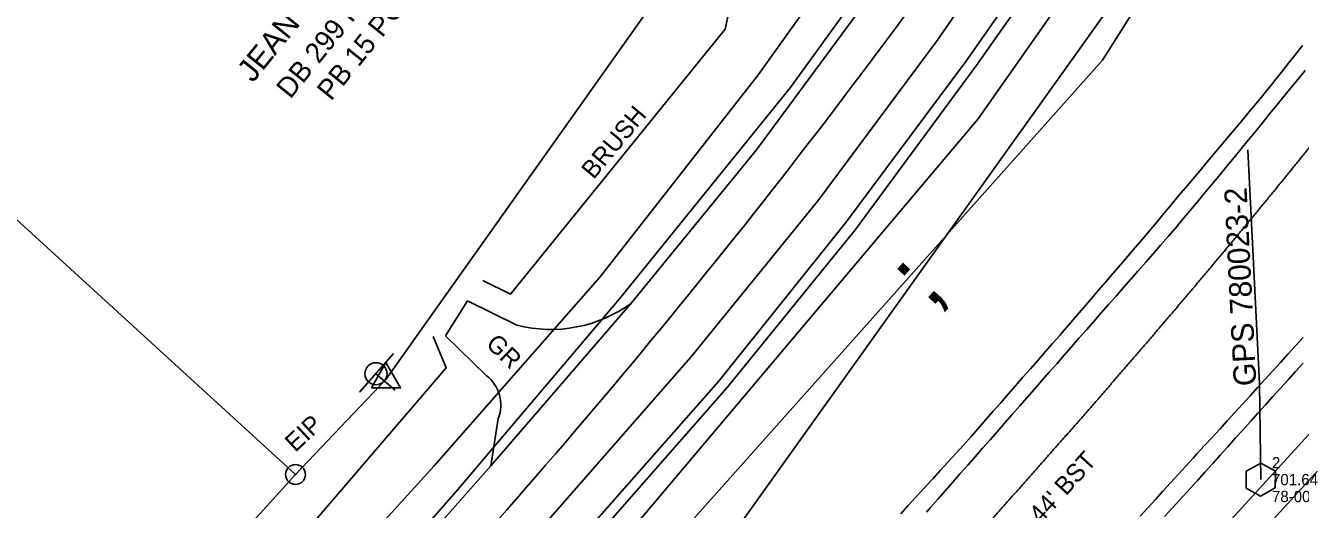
# Model space of a CAD drawing. Extents: x 1806071 to 1809844, y 912722 to 917035.
# Drawn here: x 1807079 to 1807362.2, y 914124 to 914231.7 of the extents above; entities that cross this region are included whole.
import ezdxf

# ---------------------------------------------------------------- set-up
doc = ezdxf.new("R2010")
doc.units = 0
for name, color, linetype in [('CTL GPS Vertical CELL', 7, 'Continuous'), ('CTL GPS Vertical Cogo Comment', 7, 'Continuous'), ('CTL GPS Vertical Cogo Elevation', 7, 'Continuous'), ('CTL GPS Vertical Cogo Number', 7, 'Continuous'), ('Exist Guardrail', 7, 'Continuous'), ('Exist Horizontal Alignment', 7, 'Continuous'), ('Exist Horizontal Alignment Station Label', 7, 'Continuous'), ('Exist Other Culture Fence Line', 7, 'Continuous'), ('Exist Property Deed Book Text', 7, 'Continuous'), ('Exist Property Iron Pin CELL', 7, 'Continuous'), ('Exist Property Iron Pin Text', 7, 'Continuous'), ('Exist Property Line', 7, 'Continuous'), ('Exist Property Owner Text', 7, 'Continuous'), ('Exist Right of Way Control of Access CA Symbol CELL', 7, 'Continuous'), ('Exist Right of Way Line', 7, 'Continuous'), ('Exist Right of Way Monument CELL', 7, 'Continuous'), ('Exist Roads EOP', 7, 'Continuous'), ('Exist Roads EOP Text', 7, 'Continuous'), ('Exist Roads EOT', 7, 'Continuous'), ('Exist Roads Soil', 7, 'Continuous'), ('Exist Roads Soil Text', 7, 'Continuous'), ('Exist Structure Minor Pipes RCP 24 Inch', 7, 'Continuous'), ('Exist Utilities Power Joint Use Telephone CELL', 7, 'Continuous'), ('Exist Utilities Telephone UG Cable SUE LOS B', 7, 'Continuous'), ('Exist Utilities Water UG Line SUE LOS B', 7, 'Continuous'), ('Exist Vegetation Hedge Row', 7, 'Continuous'), ('Exist Vegetation Hedge Row Text', 7, 'Continuous'), ('Exist Vegetation Woods Line', 7, 'Continuous')]:
    doc.layers.add(name, color=color, linetype=linetype)

msp = doc.modelspace()

# ---------------------------------------------------------------- linework, layer by layer
at = {"layer": 'CTL GPS Vertical CELL'}
msp.add_line((1807353.38, 914130.67), (1807353.38, 914130.67), dxfattribs=at)
msp.add_lwpolyline([(1807350.15, 914132.55), (1807353.4, 914134.36), (1807356.65, 914132.57), (1807356.6, 914128.85), (1807353.35, 914126.96), (1807350.15, 914128.77)], close=True, dxfattribs=at)
at = {"layer": 'Exist Guardrail'}
msp.add_lwpolyline([(1807384.69, 914379.78), (1807359.93, 914333.62), (1807343.17, 914305.53), (1807317.15, 914265.55), (1807287.85, 914223.71), (1807261.22, 914187.88), (1807232.95, 914152.51), (1807202.11, 914117.44), (1807168.59, 914080.84), (1807134.41, 914043.78), (1807102.1, 914008.78), (1807070.61, 913974.53), (1807044.54, 913946.19), (1807011.35, 913910), (1806981.15, 913877.01), (1806950.16, 913843.21)], dxfattribs=at)
at = {"layer": 'Exist Horizontal Alignment'}
msp.add_line((1806073.69, 912724.84), (1809374.2, 916346.52), dxfattribs=at)
for centre, radius, start, end in [((1805945.49, 915212), 1650, 317.71257, 325.04077), ((1806875.73, 914308.35), 954.93, 296.15643, 355.38963)]:
    msp.add_arc(centre, radius, start, end, dxfattribs=at)
msp.add_spline([(1807240.45, 914063.04), (1807242.27, 914065.04), (1807244.1, 914067.04), (1807245.92, 914069.04), (1807247.74, 914071.03), (1807249.56, 914073.03), (1807251.38, 914075.03), (1807253.19, 914077.03), (1807255.01, 914079.03), (1807256.83, 914081.03), (1807258.65, 914083.03), (1807260.47, 914085.03), (1807262.29, 914087.03), (1807264.1, 914089.03), (1807265.92, 914091.03), (1807267.73, 914093.03), (1807269.55, 914095.04), (1807271.36, 914097.04), (1807273.17, 914099.05), (1807274.99, 914101.05), (1807276.8, 914103.06), (1807278.61, 914105.06), (1807280.41, 914107.07), (1807282.22, 914109.08), (1807284.03, 914111.09), (1807285.83, 914113.1), (1807287.64, 914115.12), (1807289.44, 914117.13), (1807291.24, 914119.15), (1807293.04, 914121.16), (1807294.84, 914123.18), (1807296.64, 914125.2), (1807298.43, 914127.22), (1807300.22, 914129.24), (1807302.02, 914131.26), (1807303.81, 914133.29), (1807305.59, 914135.32), (1807307.38, 914137.34), (1807309.16, 914139.37), (1807310.95, 914141.41), (1807312.73, 914143.44), (1807314.51, 914145.47), (1807316.28, 914147.51), (1807318.06, 914149.55), (1807319.83, 914151.59), (1807321.6, 914153.63), (1807323.36, 914155.68), (1807325.13, 914157.73), (1807326.89, 914159.78), (1807328.65, 914161.83), (1807330.41, 914163.88), (1807332.16, 914165.94), (1807333.91, 914167.99), (1807335.66, 914170.05), (1807337.41, 914172.12), (1807339.15, 914174.18), (1807340.89, 914176.25), (1807342.63, 914178.32), (1807344.37, 914180.39), (1807346.1, 914182.47), (1807347.83, 914184.55), (1807349.55, 914186.63), (1807351.27, 914188.71), (1807352.99, 914190.79), (1807354.71, 914192.88), (1807356.42, 914194.97), (1807358.13, 914197.07), (1807359.83, 914199.17), (1807361.54, 914201.27), (1807363.23, 914203.37), (1807364.93, 914205.47), (1807366.62, 914207.58), (1807368.3, 914209.7), (1807369.99, 914211.81), (1807371.67, 914213.93)], degree=3, dxfattribs=at)
at = {"layer": 'Exist Horizontal Alignment Station Label'}
for p, q in [((1807353.1, 914152.01), (1807350.52, 914204)), ((1807353.38, 914130.67), (1807353.1, 914152.01))]:
    msp.add_line(p, q, dxfattribs=at)
at = {"layer": 'Exist Other Culture Fence Line'}
msp.add_lwpolyline([(1806951.65, 913841.13), (1806983.44, 913875.99), (1807013.14, 913908.4), (1807047.06, 913945.66), (1807072.1, 913972.65), (1807103.97, 914007.22), (1807136.36, 914042.6), (1807170.27, 914079.29), (1807203.63, 914115.49), (1807234.9, 914151.15), (1807263.39, 914186.29), (1807290.32, 914222.94), (1807319.14, 914263.94), (1807345.33, 914304.29), (1807362.24, 914332.3), (1807387.67, 914379.81), (1807420.06, 914449.08)], dxfattribs=at)
at = {"layer": 'Exist Property Iron Pin CELL'}
for radius in [2.2, 0.0707]:
    msp.add_circle((1807138.99, 914131.81), radius, dxfattribs=at)
at = {"layer": 'Exist Property Line'}
msp.add_line((1807138.99, 914131.81), (1806985.27, 914272.46), dxfattribs=at)
at = {"layer": 'Exist Right of Way Control of Access CA Symbol CELL'}
msp.add_line((1807279.4, 914178.99), (1807279.4, 914178.99), dxfattribs=at)
at = {"layer": 'Exist Right of Way Line'}
for p, q in [((1807213.85, 914087.29), (1807408.46, 914360.2)), ((1807138.99, 914131.81), (1807072.09, 914058.26))]:
    msp.add_line(p, q, dxfattribs=at)
msp.add_lwpolyline([(1807235.62, 914261.04), (1807159.09, 914152.97), (1807138.99, 914131.81)], dxfattribs=at)
at = {"layer": 'Exist Right of Way Monument CELL'}
msp.add_line((1807159.09, 914152.97), (1807159.09, 914152.97), dxfattribs=at)
msp.add_lwpolyline([(1807155.84, 914151.08), (1807159.09, 914156.72), (1807162.34, 914151.08)], close=True, dxfattribs=at)
at = {"layer": 'Exist Roads EOP'}
msp.add_line((1807182.36, 914133.76), (1807213.6, 914169.96), dxfattribs=at)
for points in [[(1807255.1, 914192.79), (1807281.5, 914228.36), (1807309.99, 914269.65)], [(1807213.6, 914169.96), (1807241.42, 914204.04), (1807266.24, 914237.81), (1807268.12, 914240.61)], [(1807362.69, 914227.2), (1807361.13, 914225.24), (1807359.58, 914223.28), (1807358.02, 914221.33), (1807356.47, 914219.37), (1807356.32, 914219.18), (1807354.74, 914217.25), (1807353.16, 914215.32), (1807351.57, 914213.38), (1807351.14, 914212.85), (1807349.53, 914210.94), (1807347.93, 914209.02), (1807346.32, 914207.1), (1807344.72, 914205.19), (1807343.11, 914203.27), (1807341.51, 914201.36), (1807339.9, 914199.44), (1807338.3, 914197.52), (1807336.69, 914195.61), (1807335.08, 914193.69), (1807333.48, 914191.77), (1807331.87, 914189.86), (1807330.27, 914187.94), (1807328.66, 914186.02), (1807327.11, 914184.17), (1807325.48, 914182.27), (1807323.85, 914180.37), (1807322.23, 914178.47), (1807320.6, 914176.58), (1807318.97, 914174.68), (1807317.34, 914172.78), (1807315.72, 914170.88), (1807314.09, 914168.99), (1807312.46, 914167.09), (1807310.83, 914165.19), (1807309.21, 914163.29), (1807308.81, 914162.83), (1807307.16, 914160.95), (1807305.51, 914159.07), (1807303.87, 914157.19), (1807302.22, 914155.31), (1807300.57, 914153.43), (1807298.93, 914151.55), (1807297.28, 914149.67), (1807295.63, 914147.79), (1807293.98, 914145.9), (1807292.34, 914144.02), (1807290.69, 914142.14), (1807289.04, 914140.26), (1807287.34, 914138.32), (1807285.65, 914136.47), (1807283.97, 914134.62), (1807282.28, 914132.78), (1807280.6, 914130.93), (1807280.16, 914130.45), (1807278.48, 914128.6), (1807276.8, 914126.75), (1807275.11, 914124.9), (1807273.43, 914123.05)], [(1806945.72, 913846.49), (1806977.27, 913880.57), (1807007.52, 913913.78), (1807040.2, 913949.97), (1807065.65, 913978.22), (1807097.4, 914012.45), (1807129.79, 914047.7), (1807164, 914085.55), (1807196.13, 914122.85), (1807226.78, 914157.88), (1807255.1, 914192.79)], [(1807332, 914122.47), (1807333.69, 914124.31), (1807335.38, 914126.15), (1807337.07, 914127.99), (1807337.72, 914128.7), (1807339.39, 914130.56), (1807341.06, 914132.42), (1807342.73, 914134.28), (1807344.4, 914136.14), (1807346.07, 914138), (1807347.74, 914139.86), (1807349.41, 914141.71), (1807351.09, 914143.57), (1807352.76, 914145.43), (1807354.43, 914147.29), (1807356.1, 914149.15), (1807357.77, 914151.01), (1807359.44, 914152.87), (1807361.11, 914154.73), (1807362.79, 914156.59)], [(1807052.3, 913989.42), (1807084.47, 914024.84), (1807116.4, 914060.3), (1807150.94, 914098.08), (1807182.36, 914133.76)]]:
    msp.add_lwpolyline(points, dxfattribs=at)
at = {"layer": 'Exist Roads EOT'}
for points in [[(1807279.13, 914123.44), (1807280.07, 914124.49), (1807281.72, 914126.37), (1807283.36, 914128.25), (1807285.01, 914130.13), (1807286.66, 914132.01), (1807288.31, 914133.89), (1807289.95, 914135.77), (1807291.6, 914137.65), (1807293.25, 914139.53), (1807294.89, 914141.41), (1807296.54, 914143.29), (1807298.19, 914145.17), (1807299.84, 914147.05), (1807301.48, 914148.93), (1807303.13, 914150.81), (1807304.78, 914152.7), (1807306.42, 914154.58), (1807308.07, 914156.46), (1807309.72, 914158.34), (1807311.37, 914160.22), (1807313.01, 914162.1), (1807314.66, 914163.98), (1807316.31, 914165.86), (1807317.96, 914167.74), (1807319.6, 914169.62), (1807321.25, 914171.5), (1807322.9, 914173.38), (1807324.54, 914175.26), (1807326.19, 914177.14), (1807327.84, 914179.02), (1807329.49, 914180.9), (1807331.13, 914182.79), (1807332.83, 914184.72), (1807334.43, 914186.64), (1807336.03, 914188.56), (1807337.63, 914190.48), (1807339.23, 914192.4), (1807340.84, 914194.32), (1807342.44, 914196.24), (1807344.04, 914198.16), (1807345.64, 914200.07), (1807345.89, 914200.37), (1807347.46, 914202.31), (1807349.04, 914204.24), (1807350.62, 914206.18), (1807352.2, 914208.12), (1807353.78, 914210.06), (1807355.36, 914212), (1807356.94, 914213.94), (1807358.52, 914215.87), (1807360.09, 914217.81), (1807361.67, 914219.75), (1807363.25, 914221.69)], [(1807326.62, 914122.54), (1807328.3, 914124.39), (1807329.98, 914126.24), (1807331.67, 914128.09), (1807333.35, 914129.93), (1807335.03, 914131.78), (1807336.71, 914133.63), (1807338.4, 914135.48), (1807339.22, 914136.39), (1807340.91, 914138.24), (1807342.59, 914140.08), (1807344.28, 914141.93), (1807345.96, 914143.78), (1807347.65, 914145.63), (1807349.33, 914147.47), (1807351.01, 914149.32), (1807352.7, 914151.17), (1807354.38, 914153.02), (1807356.07, 914154.86), (1807357.75, 914156.71), (1807359.43, 914158.56), (1807361.12, 914160.41), (1807362.8, 914162.25)]]:
    msp.add_lwpolyline(points, dxfattribs=at)
at = {"layer": 'Exist Roads Soil'}
for p, q in [((1807172.32, 914162.65), (1807177.23, 914170.46)), ((1807188.16, 914165.04), (1807177.23, 914170.46)), ((1807181.37, 914153.83), (1807172.32, 914162.65)), ((1807182.36, 914133.76), (1807184.03, 914144.24))]:
    msp.add_line(p, q, dxfattribs=at)
for centre, major_axis, ratio, start_param, end_param in [((1807195.71, 914194.22), (29.39, -6.7), 0.999951, 4.683135, 5.571692), ((1807176.31, 914147.26), (6.52, 5.13), 0.998641, 5.242809, 6.530809)]:
    msp.add_ellipse(centre, major_axis=major_axis, ratio=ratio, start_param=start_param, end_param=end_param, dxfattribs=at)
at = {"layer": 'Exist Structure Minor Pipes RCP 24 Inch'}
msp.add_line((1807298.31, 914058.62), (1807569.06, 914354.69), dxfattribs=at)
at = {"layer": 'Exist Utilities Power Joint Use Telephone CELL'}
msp.add_line((1807156.87, 914154.23), (1807156.87, 914154.23), dxfattribs=at)
msp.add_lwpolyline([(1807160.76, 914158.71), (1807153.3, 914150.18), (1807156.85, 914154.24), (1807161.12, 914150.54)], dxfattribs=at)
msp.add_circle((1807156.87, 914154.22), 2.45, dxfattribs=at)
at = {"layer": 'Exist Utilities Telephone UG Cable SUE LOS B'}
msp.add_lwpolyline([(1807023.9, 913961.8), (1807061.37, 914001.94), (1807102.69, 914047), (1807137.71, 914085.93), (1807174.65, 914128.03), (1807210.98, 914170.85), (1807248.89, 914217.78), (1807283.52, 914265.76), (1807309.87, 914305.3), (1807337.23, 914356.7), (1807347.09, 914377.33), (1807353.51, 914402.93), (1807353.58, 914404.22)], dxfattribs=at)
at = {"layer": 'Exist Utilities Water UG Line SUE LOS B'}
msp.add_lwpolyline([(1806934.01, 913876.79), (1806942.74, 913886.69), (1806979.16, 913924.81), (1807020.1, 913968.31), (1807057.54, 914008.89), (1807096.91, 914053.52), (1807130.38, 914090.29), (1807169.81, 914133.74), (1807206.7, 914175.78), (1807241.81, 914220.76), (1807276.28, 914269.15), (1807304.66, 914309.76), (1807334.37, 914357.07), (1807347.65, 914376.89), (1807360.82, 914396.29), (1807368.31, 914413.26), (1807386.71, 914435.17), (1807414.54, 914474.63), (1807431.02, 914499.69)], dxfattribs=at)
at = {"layer": 'Exist Vegetation Hedge Row'}
for points in [[(1807235.73, 914237.2), (1807234.42, 914230.83), (1807186.75, 914171.96), (1807180.61, 914174.94)], [(1807169.58, 914162.49), (1807172.43, 914155.55), (1807089.9, 914059.13), (1807082.69, 914064.35)]]:
    msp.add_lwpolyline(points, dxfattribs=at)
at = {"layer": 'Exist Vegetation Woods Line'}
for points in [[(1806971.08, 913843.97), (1807045.94, 913927.81), (1807101.46, 913994.42), (1807207.65, 914112.42), (1807290.59, 914210.89), (1807368.19, 914321.69), (1807398.66, 914385.06), (1807410.19, 914406.72), (1807422.39, 914418.16), (1807425.9, 914407.59)], [(1807425.9, 914407.59), (1807384.1, 914328.34), (1807318.27, 914223.99), (1807197.19, 914088.02), (1807090.43, 913967.23), (1807035.17, 913899.75), (1806979.91, 913836.15)]]:
    msp.add_lwpolyline(points, dxfattribs=at)

# ---------------------------------------------------------------- texts
at = {"layer": 'CTL GPS Vertical Cogo Comment'}
msp.add_text('78-0023-GPS2', height=2.5, dxfattribs=at).set_placement((1807355.88, 914125.68))
at = {"layer": 'CTL GPS Vertical Cogo Elevation'}
msp.add_text('701.64', height=2.5, dxfattribs=at).set_placement((1807355.88, 914129.43))
at = {"layer": 'CTL GPS Vertical Cogo Number'}
msp.add_text('2', height=2.5, dxfattribs=at).set_placement((1807355.88, 914133.18))
at = {"layer": 'Exist Horizontal Alignment Station Label'}
msp.add_text('GPS 780023-2', height=5, rotation=92.8422, dxfattribs=at).set_placement((1807352.43, 914151.6))
at = {"layer": 'Exist Property Deed Book Text'}
for s, p in [('DB 299 PG 399', (1807137.87, 914215.17)), ('PB 15 PG 73', (1807146.9, 914214.73))]:
    msp.add_text(s, height=4.5, rotation=51.2029, dxfattribs=at).set_placement(p)
at = {"layer": 'Exist Property Iron Pin Text'}
msp.add_text('EIP', height=4, rotation=43.1258, dxfattribs=at).set_placement((1807138.95, 914136.62))
at = {"layer": 'Exist Property Owner Text'}
msp.add_text('JEAN A. McRAE', height=5, rotation=51.1111, dxfattribs=at).set_placement((1807129.53, 914218.78))
at = {"layer": 'Exist Right of Way Control of Access CA Symbol CELL'}
msp.add_text(';', height=15, rotation=47.6565, dxfattribs=at).set_placement((1807279.89, 914168.4))
at = {"layer": 'Exist Roads EOP Text'}
msp.add_text("US 29 SOUTH    44' BST", height=4, rotation=47.8413, dxfattribs=at).set_placement((1807276.94, 914090.25))
at = {"layer": 'Exist Roads Soil Text'}
msp.add_text('GR', height=4, rotation=315.7179, dxfattribs=at).set_placement((1807181.06, 914160.6))
at = {"layer": 'Exist Vegetation Hedge Row Text'}
msp.add_text('BRUSH', height=4, rotation=50.201, dxfattribs=at).set_placement((1807205.22, 914197.29))

doc.saveas('drawing.dxf')
